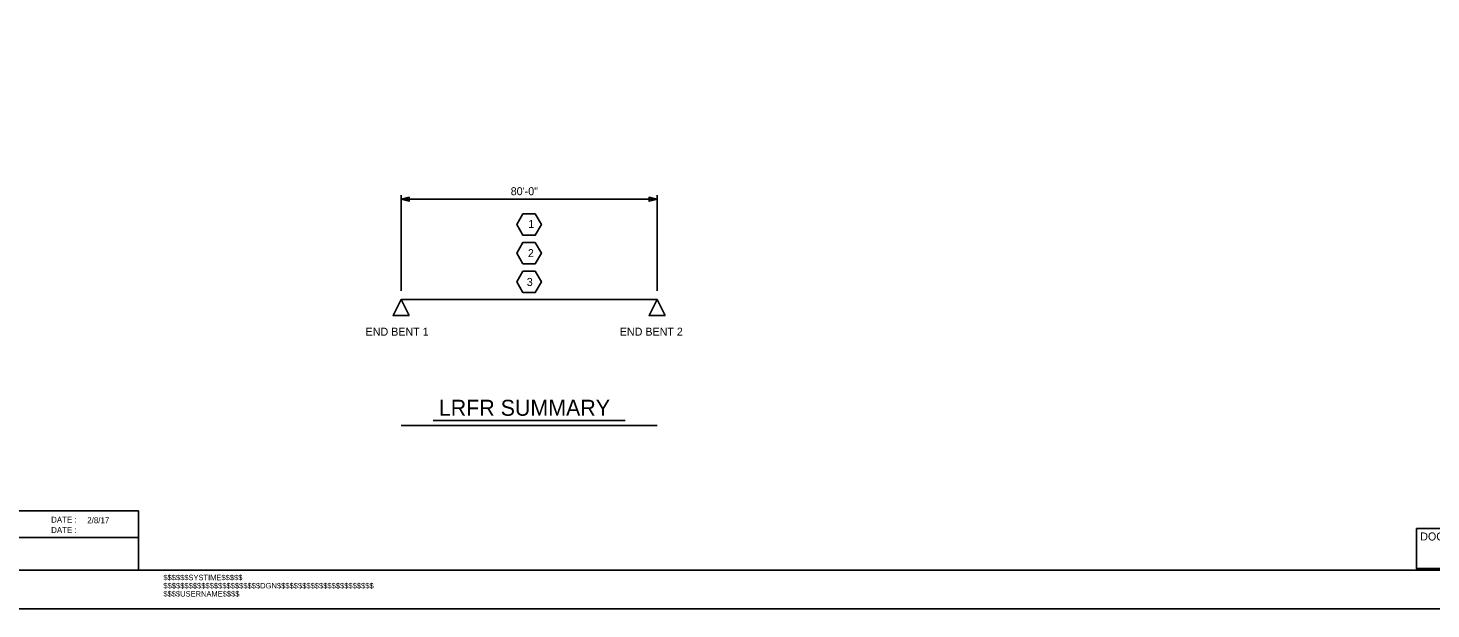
# Model space of a CAD drawing. Extents: x -190 to 360, y 729 to 1065.
# Drawn here: x 7.6 to 226.8, y 729.5 to 820.2 of the extents above; entities that cross this region are included whole.
import ezdxf

# ---------------------------------------------------------------- set-up
doc = ezdxf.new("R2010")
doc.units = 0
for name, color, linetype in [('Arrowhead Terminators', 7, 'Continuous'), ('Dimension Lines', 7, 'Continuous'), ('Mis Object Lines', 7, 'Continuous'), ('Plan Sheet', 7, 'Continuous'), ('Plan Sheet CELL', 7, 'Continuous'), ('Plot Label CELL', 7, 'Continuous'), ('Plot Shape CELL', 7, 'Continuous'), ('Sheet Sticker Exception Certification CELL', 7, 'Continuous'), ('Sub End Bent Cap Lines CELL', 7, 'Continuous'), ('Table Border', 7, 'Continuous'), ('Text', 7, 'Continuous'), ('Title Text', 7, 'Continuous')]:
    doc.layers.add(name, color=color, linetype=linetype)

# ---------------------------------------------------------------- blocks, each defined once
blk = doc.blocks.new('AH')
at = {"layer": 'Sub End Bent Cap Lines CELL'}
blk.add_lwpolyline([(0, 0), (-1.25, 0.31), (-1.25, -0.31)], close=True, dxfattribs=at)

msp = doc.modelspace()

# ---------------------------------------------------------------- linework, layer by layer
at = {"layer": 'Dimension Lines'}
for p, q in [((65.92, 779.19), (65.92, 794.14)), ((65.92, 793.48), (105.92, 793.48)), ((105.92, 779.19), (105.92, 794.14))]:
    msp.add_line(p, q, dxfattribs=at)
at = {"layer": 'Mis Object Lines'}
msp.add_line((65.92, 777.8), (105.92, 777.8), dxfattribs=at)
for points in [[(67.17, 775.3), (64.67, 775.3), (65.92, 777.8)], [(107.17, 775.3), (104.67, 775.3), (105.92, 777.8)]]:
    msp.add_lwpolyline(points, close=True, dxfattribs=at)
at = {"layer": 'Plan Sheet'}
for p, q in [((-16.76, 744.81), (24.88, 744.81)), ((24.88, 735.55), (24.88, 744.81)), ((24.88, 744.81), (24.88, 744.81)), ((24.88, 740.63), (-16.76, 740.63))]:
    msp.add_line(p, q, dxfattribs=at)
at = {"layer": 'Plan Sheet CELL'}
msp.add_line((-16.76, 735.55), (303.24, 735.55), dxfattribs=at)
at = {"layer": 'Plot Shape CELL'}
msp.add_lwpolyline([(-27.3, 949.49), (303.33, 949.49), (303.33, 729.49), (-27.3, 729.49)], close=True, dxfattribs=at)
at = {"layer": 'Sheet Sticker Exception Certification CELL'}
msp.add_lwpolyline([(224.54, 742.07), (253.03, 742.07), (253.03, 735.8), (224.54, 735.8)], close=True, dxfattribs=at)
at = {"layer": 'Table Border'}
for points in [[(86.88, 791.2), (84.96, 791.2), (83.99, 789.53), (84.96, 787.87), (86.88, 787.87), (87.84, 789.53)], [(86.88, 786.74), (84.96, 786.74), (83.99, 785.07), (84.96, 783.4), (86.88, 783.4), (87.84, 785.07)], [(86.88, 782.24), (84.96, 782.24), (83.99, 780.57), (84.96, 778.9), (86.88, 778.9), (87.84, 780.57)]]:
    msp.add_lwpolyline(points, close=True, dxfattribs=at)
at = {"layer": 'Title Text'}
for p, q in [((100.92, 758.91), (70.92, 758.91)), ((105.92, 758.16), (65.92, 758.16))]:
    msp.add_line(p, q, dxfattribs=at)

# ---------------------------------------------------------------- block references
at = {"layer": 'Arrowhead Terminators', "rotation": 180}
msp.add_blockref('AH', (65.92, 793.48), dxfattribs=at)
at = {"layer": 'Arrowhead Terminators'}
msp.add_blockref('AH', (105.92, 793.48), dxfattribs=at)

# ---------------------------------------------------------------- texts
at = {"layer": 'Plan Sheet'}
for p in [(11.26, 742.96), (11.26, 741.36)]:
    msp.add_text('DATE :', height=0.925, dxfattribs=at).set_placement(p)
at = {"layer": 'Plot Label CELL'}
for s, height, p in [('$$$$$$SYSTIME$$$$$', 0.8504, (28.79, 733.97)), ('$$$$$$$$$$$$$$$$$$$$$$$DGN$$$$$$$$$$$$$$$$$$$$$$$', 0.8556, (28.79, 732.69)), ('$$$$USERNAME$$$$', 0.8504, (28.79, 731.42))]:
    msp.add_text(s, height=height, dxfattribs=at).set_placement(p)
at = {"layer": 'Sheet Sticker Exception Certification CELL'}
msp.add_text('DOCUMENT NOT CONSIDERED', height=1.2472, dxfattribs=at).set_placement((225.13, 740.18))
at = {"layer": 'Text'}
for s, height, p in [('80\'-0"', 1.25, (83.05, 794.11)), ('1', 1.25, (85.8, 788.99)), ('2', 1.25, (85.73, 784.44)), ('3', 1.25, (85.56, 779.94)), ('END BENT 1', 1.25, (60.38, 772.17)), ('END BENT 2', 1.25, (100.09, 772.17)), ('2/8/17', 0.925, (16.9, 742.88))]:
    msp.add_text(s, height=height, dxfattribs=at).set_placement(p)
at = {"layer": 'Title Text'}
msp.add_text('LRFR SUMMARY', height=2.5, dxfattribs=at).set_placement((71.82, 759.66))

doc.saveas('drawing.dxf')
